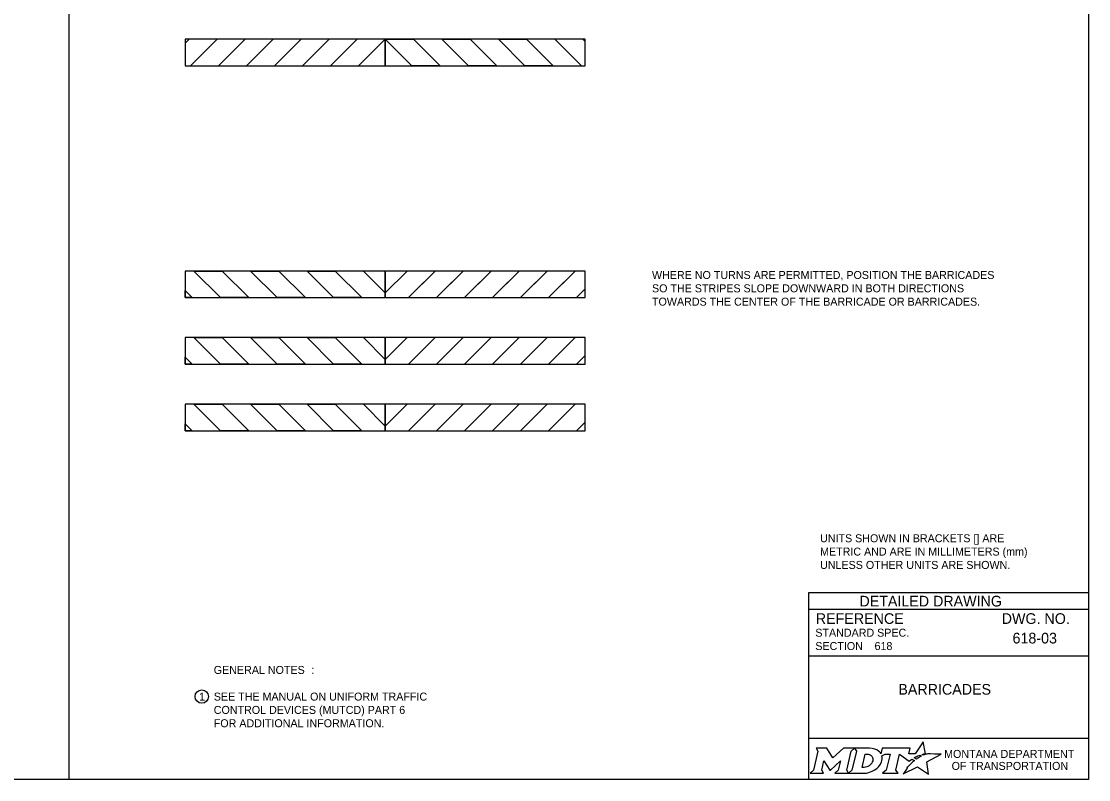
# Model space of a CAD drawing. Extents: x 49991.4 to 50021, y 49987.6 to 50011.4.
# Drawn here: x 50008.75 to 50016.75, y 49987.8 to 49993.49 of the extents above; entities that cross this region are included whole.
import ezdxf

# ---------------------------------------------------------------- set-up
doc = ezdxf.new("R2010")
doc.units = 0
for name, color, linetype in [('Default', 7, 'Continuous'), ('Level 1', 7, 'Continuous'), ('Level 2', 7, 'Continuous'), ('Level 5', 7, 'Continuous')]:
    doc.layers.add(name, color=color, linetype=linetype)

msp = doc.modelspace()

# ---------------------------------------------------------------- linework, layer by layer
at = {"layer": 'Default'}
for points in [[(50015.5126, 49987.9811), (50015.5023, 49987.9867), (50015.5139, 49987.9895), (50015.5255, 49987.9915), (50015.5081, 49988.0816), (50015.4486, 49987.9903), (50015.4013, 49987.9896), (50015.4116, 49988.0337), (50015.2024, 49988.0338), (50015.1923, 49987.9913), (50015.1865, 49987.9996)], [(50014.7056, 49988.0338), (50014.7197, 49988.0104), (50014.6862, 49987.8671), (50014.6605, 49987.8446), (50014.7621, 49987.8446), (50014.7486, 49987.8674), (50014.7648, 49987.9375), (50014.8085, 49987.8685), (50014.8138, 49987.8685), (50014.8889, 49987.938), (50014.8725, 49987.8669), (50014.8478, 49987.8449), (50014.9494, 49987.8449), (50014.9356, 49987.8682), (50014.9688, 49988.0106)], [(50014.9688, 49988.0106), (50014.9941, 49988.0338), (50014.9117, 49988.0338), (50014.8321, 49987.9608), (50014.7876, 49988.0335), (50014.7056, 49988.0338)], [(50015.1077, 49988.0338), (50014.9941, 49988.0338), (50015.0088, 49988.0109), (50014.9749, 49987.8671), (50014.9494, 49987.8449), (50015.06, 49987.8449)], [(50015.1317, 49987.9471), (50015.1305, 49987.939), (50015.1273, 49987.9297), (50015.1231, 49987.9215), (50015.1175, 49987.914), (50015.111, 49987.9071), (50015.1031, 49987.9008), (50015.0948, 49987.8961), (50015.0857, 49987.8922), (50015.0766, 49987.8899), (50015.0674, 49987.889), (50015.0515, 49987.889), (50015.0751, 49987.989), (50015.0911, 49987.989), (50015.0987, 49987.9884), (50015.1063, 49987.9865), (50015.1129, 49987.9835), (50015.119, 49987.9793), (50015.1238, 49987.9743), (50015.1275, 49987.9683), (50015.1302, 49987.9621), (50015.1318, 49987.9547), (50015.1318, 49987.9517), (50015.1317, 49987.9471)], [(50015.1991, 49987.9747), (50015.2237, 49987.9878), (50015.2606, 49987.9878), (50015.232, 49987.8673), (50015.2045, 49987.8446), (50015.3207, 49987.8446), (50015.3037, 49987.8675), (50015.3319, 49987.9877), (50015.4032, 49987.936), (50015.4243, 49987.9511), (50015.444, 49987.9402)], [(50015.3882, 49987.8843), (50015.3729, 49987.8599), (50015.3682, 49987.8524), (50015.3624, 49987.8438), (50015.3601, 49987.8395), (50015.4654, 49987.8926), (50015.5493, 49987.8375), (50015.5362, 49987.9302), (50015.6431, 49987.9886), (50015.5938, 49987.9894), (50015.5637, 49987.9898), (50015.5429, 49987.9901), (50015.5361, 49987.9886), (50015.5312, 49987.9874), (50015.5228, 49987.9851), (50015.5126, 49987.9811)], [(50015.4622, 49987.9535), (50015.4598, 49987.9518), (50015.4415, 49987.9614), (50015.4518, 49987.9671), (50015.4559, 49987.9693), (50015.4645, 49987.9733), (50015.4702, 49987.9759), (50015.4781, 49987.9789), (50015.4854, 49987.9816), (50015.4972, 49987.9742), (50015.4932, 49987.9721), (50015.4886, 49987.9696), (50015.4844, 49987.9674), (50015.4794, 49987.9645), (50015.4775, 49987.9634), (50015.4748, 49987.9618), (50015.4723, 49987.9604), (50015.47, 49987.9588), (50015.4674, 49987.957), (50015.4647, 49987.9552), (50015.4622, 49987.9535)], [(50015.4021, 49987.9004), (50015.4021, 49987.9004)], [(50015.1057, 49987.8522), (50015.1141, 49987.8548), (50015.1271, 49987.8602), (50015.1475, 49987.8712)]]:
    msp.add_lwpolyline(points, dxfattribs=at)
for centre, radius, start, end in [((50015.1308, 49987.9554), 0.0709, 339.53292, 15.85821), ((50015.0868, 49987.9727), 0.1183, 300.91025, 339.13831)]:
    msp.add_arc(centre, radius, start, end, dxfattribs=at)
for centre, major_axis, ratio, start_param, end_param in [((50015.1056, 49987.9864), (0.0834, -0.0037), 0.568097, 0.61298, 1.570796), ((50015.1612, 49987.9937), (0.0361, -0.0295), 0.469099, 1.225588, 1.570796), ((50015.3952, 49987.8923), (-0.00694, -0.00806), 0.008222, 0, 3.137361), ((50015.4119, 49987.9106), (-0.0098, -0.0102), 0.016458, 3.141593, 6.279097), ((50015.4329, 49987.9305), (-0.0112, -0.0097), 0.021651, 3.157348, 6.283185), ((50015.0603, 49987.9932), (0, 0.1484), 0.987302, 3.139398, 3.456847)]:
    msp.add_ellipse(centre, major_axis=major_axis, ratio=ratio, start_param=start_param, end_param=end_param, dxfattribs=at)
at = {"layer": 'Level 1'}
for p, q in [((50011.6752, 49993.153), (50011.4756, 49993.353)), ((50011.8872, 49993.153), (50011.6876, 49993.353)), ((50011.6876, 49993.353), (50011.8872, 49993.153)), ((50012.0991, 49993.153), (50011.8995, 49993.353)), ((50012.0991, 49993.153), (50011.8995, 49993.353)), ((50012.3111, 49993.153), (50012.1115, 49993.353)), ((50012.1115, 49993.353), (50012.3111, 49993.153)), ((50012.523, 49993.153), (50012.3234, 49993.353)), ((50012.523, 49993.153), (50012.3234, 49993.353)), ((50012.735, 49993.153), (50012.5354, 49993.353)), ((50012.5354, 49993.353), (50012.735, 49993.153)), ((50010.2404, 49991.4131), (50010.0408, 49991.6131)), ((50010.2404, 49991.4131), (50010.0408, 49991.6131)), ((50010.4524, 49991.4131), (50010.2528, 49991.6131)), ((50010.2528, 49991.6131), (50010.4524, 49991.4131)), ((50010.6643, 49991.4131), (50010.4647, 49991.6131)), ((50010.6643, 49991.4131), (50010.4647, 49991.6131)), ((50010.8763, 49991.4131), (50010.6767, 49991.6131)), ((50010.6767, 49991.6131), (50010.8763, 49991.4131)), ((50011.0882, 49991.4131), (50010.8886, 49991.6131)), ((50011.0882, 49991.4131), (50010.8886, 49991.6131)), ((50011.3002, 49991.4131), (50011.1006, 49991.6131)), ((50011.1006, 49991.6131), (50011.3002, 49991.4131)), ((50011.4756, 49991.4497), (50011.3125, 49991.6131)), ((50011.3125, 49991.6131), (50011.4756, 49991.4497)), ((50010.0285, 49991.4131), (50009.9756, 49991.4661)), ((50009.9756, 49991.4661), (50010.0285, 49991.4131)), ((50010.2404, 49990.9131), (50010.0408, 49991.1131)), ((50010.2404, 49990.9131), (50010.0408, 49991.1131)), ((50010.4524, 49990.9131), (50010.2528, 49991.1131)), ((50010.2528, 49991.1131), (50010.4524, 49990.9131)), ((50010.6643, 49990.9131), (50010.4647, 49991.1131)), ((50010.6643, 49990.9131), (50010.4647, 49991.1131)), ((50010.8763, 49990.9131), (50010.6767, 49991.1131)), ((50010.6767, 49991.1131), (50010.8763, 49990.9131)), ((50011.0882, 49990.9131), (50010.8886, 49991.1131)), ((50011.0882, 49990.9131), (50010.8886, 49991.1131)), ((50011.3002, 49990.9131), (50011.1006, 49991.1131)), ((50011.1006, 49991.1131), (50011.3002, 49990.9131)), ((50011.4756, 49990.9497), (50011.3125, 49991.1131)), ((50011.3125, 49991.1131), (50011.4756, 49990.9497)), ((50010.0285, 49990.9131), (50009.9756, 49990.9661)), ((50009.9756, 49990.9661), (50010.0285, 49990.9131)), ((50010.2404, 49990.4131), (50010.0408, 49990.6131)), ((50010.2404, 49990.4131), (50010.0408, 49990.6131)), ((50010.4524, 49990.4131), (50010.2528, 49990.6131)), ((50010.2528, 49990.6131), (50010.4524, 49990.4131)), ((50010.6643, 49990.4131), (50010.4647, 49990.6131)), ((50010.6643, 49990.4131), (50010.4647, 49990.6131)), ((50010.8763, 49990.4131), (50010.6767, 49990.6131)), ((50010.6767, 49990.6131), (50010.8763, 49990.4131)), ((50011.0882, 49990.4131), (50010.8886, 49990.6131)), ((50011.0882, 49990.4131), (50010.8886, 49990.6131)), ((50011.3002, 49990.4131), (50011.1006, 49990.6131)), ((50011.1006, 49990.6131), (50011.3002, 49990.4131)), ((50011.4756, 49990.4497), (50011.3125, 49990.6131)), ((50011.3125, 49990.6131), (50011.4756, 49990.4497)), ((50010.0285, 49990.4131), (50009.9756, 49990.4661)), ((50009.9756, 49990.4661), (50010.0285, 49990.4131))]:
    msp.add_line(p, q, dxfattribs=at)
for points in [[(49999.3835, 49998.9992), (50016.7501, 49998.9992), (50016.7501, 49987.7988), (49999.3835, 49987.7988)], [(50011.4756, 49993.353), (50009.9756, 49993.353), (50009.9756, 49993.153), (50011.4756, 49993.153)], [(50012.9756, 49993.353), (50011.4756, 49993.353), (50011.4756, 49993.153), (50012.9756, 49993.153)], [(50011.4756, 49991.6131), (50009.9756, 49991.6131), (50009.9756, 49991.4131), (50011.4756, 49991.4131)], [(50012.9756, 49991.6131), (50011.4756, 49991.6131), (50011.4756, 49991.4131), (50012.9756, 49991.4131)], [(50011.4756, 49991.1131), (50009.9756, 49991.1131), (50009.9756, 49990.9131), (50011.4756, 49990.9131)], [(50012.9756, 49991.1131), (50011.4756, 49991.1131), (50011.4756, 49990.9131), (50012.9756, 49990.9131)], [(50011.4756, 49990.6131), (50009.9756, 49990.6131), (50009.9756, 49990.4131), (50011.4756, 49990.4131)], [(50012.9756, 49990.6131), (50011.4756, 49990.6131), (50011.4756, 49990.4131), (50012.9756, 49990.4131)]]:
    msp.add_lwpolyline(points, close=True, dxfattribs=at)
for points in [[(50011.4756, 49993.353), (50011.6876, 49993.353)], [(50011.8995, 49993.353), (50012.1115, 49993.353)], [(50012.3234, 49993.353), (50012.5354, 49993.353)], [(50011.8872, 49993.153), (50011.6752, 49993.153)], [(50012.3111, 49993.153), (50012.0991, 49993.153)], [(50012.735, 49993.153), (50012.523, 49993.153)], [(50010.0408, 49991.6131), (50010.2528, 49991.6131)], [(50010.4647, 49991.6131), (50010.6767, 49991.6131)], [(50010.8886, 49991.6131), (50011.1006, 49991.6131)], [(50011.4756, 49991.4497), (50011.4756, 49991.6131), (50011.3125, 49991.6131)], [(50010.0285, 49991.4131), (50009.9756, 49991.4131), (50009.9756, 49991.4661)], [(50010.4524, 49991.4131), (50010.2404, 49991.4131)], [(50010.8763, 49991.4131), (50010.6643, 49991.4131)], [(50011.3002, 49991.4131), (50011.0882, 49991.4131)], [(50010.0408, 49991.1131), (50010.2528, 49991.1131)], [(50010.4647, 49991.1131), (50010.6767, 49991.1131)], [(50010.8886, 49991.1131), (50011.1006, 49991.1131)], [(50011.4756, 49990.9497), (50011.4756, 49991.1131), (50011.3125, 49991.1131)], [(50010.0285, 49990.9131), (50009.9756, 49990.9131), (50009.9756, 49990.9661)], [(50010.4524, 49990.9131), (50010.2404, 49990.9131)], [(50010.8763, 49990.9131), (50010.6643, 49990.9131)], [(50011.3002, 49990.9131), (50011.0882, 49990.9131)], [(50010.0408, 49990.6131), (50010.2528, 49990.6131)], [(50010.4647, 49990.6131), (50010.6767, 49990.6131)], [(50010.8886, 49990.6131), (50011.1006, 49990.6131)], [(50011.4756, 49990.4497), (50011.4756, 49990.6131), (50011.3125, 49990.6131)], [(50010.0285, 49990.4131), (50009.9756, 49990.4131), (50009.9756, 49990.4661)], [(50010.4524, 49990.4131), (50010.2404, 49990.4131)], [(50010.8763, 49990.4131), (50010.6643, 49990.4131)], [(50011.3002, 49990.4131), (50011.0882, 49990.4131)]]:
    msp.add_lwpolyline(points, dxfattribs=at)
at = {"layer": 'Level 2'}
for p, q in [((50009.1021, 49998.9973), (50009.1021, 49987.7969)), ((50011.4756, 49991.4497), (50011.639, 49991.6131)), ((50011.649, 49991.4131), (50011.849, 49991.6131)), ((50011.6856, 49991.4497), (50011.849, 49991.6131)), ((50011.859, 49991.4131), (50012.059, 49991.6131)), ((50011.8956, 49991.4497), (50012.059, 49991.6131)), ((50012.069, 49991.4131), (50012.269, 49991.6131)), ((50012.1056, 49991.4497), (50012.269, 49991.6131)), ((50012.279, 49991.4131), (50012.479, 49991.6131)), ((50012.3156, 49991.4497), (50012.479, 49991.6131)), ((50012.489, 49991.4131), (50012.689, 49991.6131)), ((50012.5256, 49991.4497), (50012.689, 49991.6131)), ((50012.699, 49991.4131), (50012.899, 49991.6131)), ((50012.7356, 49991.4497), (50012.899, 49991.6131)), ((50012.909, 49991.4131), (50012.9756, 49991.4797)), ((50011.4756, 49990.9497), (50011.639, 49991.1131)), ((50011.649, 49990.9131), (50011.849, 49991.1131)), ((50011.6856, 49990.9497), (50011.849, 49991.1131)), ((50011.859, 49990.9131), (50012.059, 49991.1131)), ((50011.8956, 49990.9497), (50012.059, 49991.1131)), ((50012.069, 49990.9131), (50012.269, 49991.1131)), ((50012.1056, 49990.9497), (50012.269, 49991.1131)), ((50012.279, 49990.9131), (50012.479, 49991.1131)), ((50012.3156, 49990.9497), (50012.479, 49991.1131)), ((50012.489, 49990.9131), (50012.689, 49991.1131)), ((50012.5256, 49990.9497), (50012.689, 49991.1131)), ((50012.699, 49990.9131), (50012.899, 49991.1131)), ((50012.7356, 49990.9497), (50012.899, 49991.1131)), ((50012.909, 49990.9131), (50012.9756, 49990.9797)), ((50011.4756, 49990.4497), (50011.639, 49990.6131)), ((50011.649, 49990.4131), (50011.849, 49990.6131)), ((50011.6856, 49990.4497), (50011.849, 49990.6131)), ((50011.859, 49990.4131), (50012.059, 49990.6131)), ((50011.8956, 49990.4497), (50012.059, 49990.6131)), ((50012.069, 49990.4131), (50012.269, 49990.6131)), ((50012.1056, 49990.4497), (50012.269, 49990.6131)), ((50012.279, 49990.4131), (50012.479, 49990.6131)), ((50012.3156, 49990.4497), (50012.479, 49990.6131)), ((50012.489, 49990.4131), (50012.689, 49990.6131)), ((50012.5256, 49990.4497), (50012.689, 49990.6131)), ((50012.699, 49990.4131), (50012.899, 49990.6131)), ((50012.7356, 49990.4497), (50012.899, 49990.6131)), ((50012.909, 49990.4131), (50012.9756, 49990.4797))]:
    msp.add_line(p, q, dxfattribs=at)
for points in [[(50009.9756, 49993.323), (50009.9756, 49993.153), (50010.0156, 49993.153), (50010.2156, 49993.353), (50010.0056, 49993.353), (50009.9756, 49993.323)], [(50010.2256, 49993.153), (50010.4356, 49993.153), (50010.6356, 49993.353), (50010.4256, 49993.353), (50010.2256, 49993.153)], [(50010.6456, 49993.153), (50010.8556, 49993.153), (50011.0556, 49993.353), (50010.8456, 49993.353), (50010.6456, 49993.153)], [(50011.0656, 49993.153), (50011.2756, 49993.153), (50011.4756, 49993.353), (50011.2656, 49993.353), (50011.0656, 49993.153)], [(50012.9756, 49993.3347), (50012.9573, 49993.353), (50012.7473, 49993.353), (50012.9469, 49993.153), (50012.9756, 49993.153), (50012.9756, 49993.3347)], [(50011.639, 49991.6131), (50011.4756, 49991.6131), (50011.4756, 49991.4497), (50011.639, 49991.6131)], [(50011.6856, 49991.4497), (50011.649, 49991.4131), (50011.859, 49991.4131), (50011.8956, 49991.4497), (50012.059, 49991.6131), (50011.849, 49991.6131), (50011.6856, 49991.4497)], [(50012.1056, 49991.4497), (50012.069, 49991.4131), (50012.279, 49991.4131), (50012.3156, 49991.4497), (50012.479, 49991.6131), (50012.269, 49991.6131), (50012.1056, 49991.4497)], [(50012.7356, 49991.4497), (50012.899, 49991.6131), (50012.689, 49991.6131), (50012.5256, 49991.4497), (50012.489, 49991.4131), (50012.699, 49991.4131), (50012.7356, 49991.4497)], [(50012.909, 49991.4131), (50012.9756, 49991.4131), (50012.9756, 49991.4797), (50012.909, 49991.4131)], [(50011.639, 49991.1131), (50011.4756, 49991.1131), (50011.4756, 49990.9497), (50011.639, 49991.1131)], [(50011.6856, 49990.9497), (50011.649, 49990.9131), (50011.859, 49990.9131), (50011.8956, 49990.9497), (50012.059, 49991.1131), (50011.849, 49991.1131), (50011.6856, 49990.9497)], [(50012.1056, 49990.9497), (50012.069, 49990.9131), (50012.279, 49990.9131), (50012.3156, 49990.9497), (50012.479, 49991.1131), (50012.269, 49991.1131), (50012.1056, 49990.9497)], [(50012.7356, 49990.9497), (50012.899, 49991.1131), (50012.689, 49991.1131), (50012.5256, 49990.9497), (50012.489, 49990.9131), (50012.699, 49990.9131), (50012.7356, 49990.9497)], [(50012.909, 49990.9131), (50012.9756, 49990.9131), (50012.9756, 49990.9797), (50012.909, 49990.9131)], [(50011.639, 49990.6131), (50011.4756, 49990.6131), (50011.4756, 49990.4497), (50011.639, 49990.6131)], [(50011.6856, 49990.4497), (50011.649, 49990.4131), (50011.859, 49990.4131), (50011.8956, 49990.4497), (50012.059, 49990.6131), (50011.849, 49990.6131), (50011.6856, 49990.4497)], [(50012.1056, 49990.4497), (50012.069, 49990.4131), (50012.279, 49990.4131), (50012.3156, 49990.4497), (50012.479, 49990.6131), (50012.269, 49990.6131), (50012.1056, 49990.4497)], [(50012.7356, 49990.4497), (50012.899, 49990.6131), (50012.689, 49990.6131), (50012.5256, 49990.4497), (50012.489, 49990.4131), (50012.699, 49990.4131), (50012.7356, 49990.4497)], [(50012.909, 49990.4131), (50012.9756, 49990.4131), (50012.9756, 49990.4797), (50012.909, 49990.4131)]]:
    msp.add_lwpolyline(points, dxfattribs=at)
msp.add_circle((50010.0993, 49988.4201), 0.05, dxfattribs=at)
at = {"layer": 'Level 5'}
for p, q in [((50016.7501, 49989.1988), (50014.6501, 49989.1988)), ((50014.6501, 49989.1988), (50014.6501, 49987.7988)), ((50016.7501, 49989.0738), (50014.6501, 49989.0738)), ((50016.3862, 49988.8587), (50016.3862, 49988.8587)), ((50015.1444, 49988.7993), (50015.1444, 49988.7993)), ((50016.7501, 49988.7238), (50014.6501, 49988.7238)), ((50015.7001, 49988.4747), (50015.7001, 49988.4747)), ((50016.7501, 49988.1057), (50014.6501, 49988.1057))]:
    msp.add_line(p, q, dxfattribs=at)

# ---------------------------------------------------------------- texts
at = {"layer": 'Default'}
for s, p in [('MONTANA DEPARTMENT', (50015.6663, 49987.96)), ('OF TRANSPORTATION', (50015.7225, 49987.87))]:
    msp.add_text(s, height=0.06, dxfattribs=at).set_placement(p)
at = {"layer": 'Level 2'}
for s, height, p in [('WHERE NO TURNS ARE PERMITTED, POSITION THE BARRICADES', 0.06, (50013.4756, 49991.5531)), ('SO THE STRIPES SLOPE DOWNWARD IN BOTH DIRECTIONS', 0.06, (50013.4756, 49991.4531)), ('TOWARDS THE CENTER OF THE BARRICADE OR BARRICADES.', 0.06, (50013.4756, 49991.3531)), ('UNITS SHOWN IN BRACKETS [] ARE ', 0.06, (50014.736, 49989.5779)), ('METRIC AND ARE IN MILLIMETERS (mm) ', 0.06, (50014.736, 49989.4779)), ('UNLESS OTHER UNITS ARE SHOWN.', 0.06, (50014.736, 49989.3779)), ('618-03', 0.08, (50016.1794, 49988.8187)), ('618', 0.06, (50015.1444, 49988.7693)), ('GENERAL NOTES', 0.06, (50010.1893, 49988.5901)), (':', 0.06, (50010.9201, 49988.5901)), ('1', 0.06, (50010.0795, 49988.3901)), ('SEE THE MANUAL ON UNIFORM TRAFFIC', 0.06, (50010.1893, 49988.3901)), ('BARRICADES', 0.08, (50015.3229, 49988.4347)), ('CONTROL DEVICES (MUTCD) PART 6', 0.06, (50010.1893, 49988.2901)), ('FOR ADDITIONAL INFORMATION.', 0.06, (50010.1893, 49988.1901))]:
    msp.add_text(s, height=height, dxfattribs=at).set_placement(p)
at = {"layer": 'Level 5'}
for s, height, p in [('DETAILED DRAWING', 0.0799, (50015.0311, 49989.0963)), ('REFERENCE', 0.08, (50014.7037, 49988.9654)), ('DWG. NO.', 0.08, (50016.0979, 49988.9654)), ('STANDARD SPEC.', 0.06, (50014.7004, 49988.8694)), ('SECTION', 0.06, (50014.7004, 49988.7694))]:
    msp.add_text(s, height=height, dxfattribs=at).set_placement(p)

doc.saveas('drawing.dxf')
